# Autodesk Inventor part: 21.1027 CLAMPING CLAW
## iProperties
Created: 2007-01
Part Number: 21.1027 CLAMPING CLAW
Document SubType Name: Modeling
Designer: Andy Moles
Material: Aluminum-6061
Mass: 46.4698 g
Surface Area: 57.313 cm^2
Volume: 17.1475 cm^3
Density: 2.71 g/cm^3
Author: Andy Moles
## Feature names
1. Extrusion1
2. Hole1
